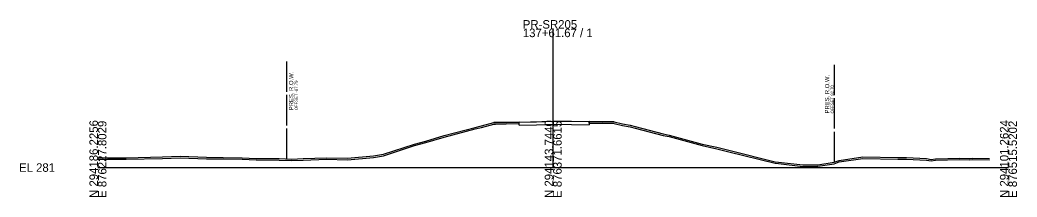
# Model space of a CAD drawing. Extents: x -26 to 875706, y -30 to 290725.
# Drawn here: x 2974.3 to 3302.8, y 2490.3 to 2548.5 of the extents above; entities that cross this region are included whole.
import ezdxf

# ---------------------------------------------------------------- set-up
doc = ezdxf.new("R2010")
doc.units = 0
for name, color, linetype in [('DESIGN - SHEET - Light Grid', 7, 'Continuous'), ('DESIGN - TYPICAL - Finished Grade and Subgrade', 7, 'Continuous'), ('SURVEY - GROUND - Bottom of Topsoil Layer', 7, 'Continuous'), ('SURVEY - GROUND - Existing Pavement Layer', 7, 'Continuous'), ('SURVEY - GROUND - Top of Ground', 7, 'Continuous'), ('SURVEY - PROPERTY - ROW Lines', 7, 'Continuous'), ('SURVEY - PROPERTY - ROW Lines Text', 7, 'Continuous')]:
    doc.layers.add(name, color=color, linetype=linetype)

msp = doc.modelspace()

# ---------------------------------------------------------------- linework, layer by layer
at = {"layer": 'DESIGN - SHEET - Light Grid'}
for p, q in [((3150, 2500), (3150, 2545.7)), ((3000, 2500), (3150, 2500)), ((3150, 2500), (3300, 2500))]:
    msp.add_line(p, q, dxfattribs=at)
at = {"layer": 'DESIGN - TYPICAL - Finished Grade and Subgrade'}
for p, q in [((3138.81, 2514.97), (3130.47, 2514.77)), ((3138.81, 2514.97), (3150, 2515.23)), ((3150, 2515.23), (3161.87, 2515.1)), ((3170.11, 2514.99), (3161.87, 2515.1))]:
    msp.add_line(p, q, dxfattribs=at)
msp.add_lwpolyline([(3139.41, 2514.98), (3139.41, 2514.97), (3139.42, 2514.97), (3139.42, 2514.98)], dxfattribs=at)
at = {"layer": 'SURVEY - GROUND - Bottom of Topsoil Layer'}
for p, q in [((3126.33, 2513.17), (3130.47, 2514.27)), ((3130.47, 2514.27), (3131.04, 2514.28)), ((3131.04, 2514.28), (3134.49, 2514.36)), ((3134.49, 2514.36), (3138.81, 2514.47)), ((3138.81, 2514.47), (3138.81, 2514.97)), ((3161.87, 2514.6), (3161.87, 2515.1)), ((3161.87, 2514.6), (3166.36, 2514.56)), ((3166.36, 2514.56), (3170.11, 2514.49)), ((3170.11, 2514.49), (3172.89, 2513.83)), ((3172.89, 2513.83), (3175.35, 2513.42)), ((3175.35, 2513.42), (3177.01, 2512.98)), ((3114.04, 2509.99), (3124.3, 2512.72)), ((3124.3, 2512.72), (3126.33, 2513.17)), ((3177.01, 2512.98), (3186.28, 2510.59)), ((3186.28, 2510.59), (3188.27, 2510.19)), ((3188.27, 2510.19), (3199.09, 2507.2)), ((3094.08, 2503.87), (3104.32, 2507.22)), ((3104.32, 2507.22), (3108.02, 2508.23)), ((3108.02, 2508.23), (3114.04, 2509.99)), ((3199.09, 2507.2), (3203.87, 2506.16)), ((3090.85, 2503.35), (3094.08, 2503.87)), ((3203.87, 2506.16), (3207.82, 2505.2)), ((3207.82, 2505.2), (3223.11, 2501.43)), ((3000, 2502.81), (3003.19, 2502.74)), ((3003.19, 2502.74), (3009.28, 2502.75)), ((3009.28, 2502.75), (3021.31, 2503.03)), ((3021.31, 2503.03), (3027.07, 2503.2)), ((3027.07, 2503.2), (3035.76, 2502.9)), ((3035.76, 2502.9), (3041.27, 2502.84)), ((3041.27, 2502.84), (3047.54, 2502.75)), ((3047.54, 2502.75), (3052.19, 2502.51)), ((3052.19, 2502.51), (3059.75, 2502.48)), ((3059.75, 2502.48), (3063.86, 2502.3)), ((3063.86, 2502.3), (3067.57, 2502.48)), ((3067.57, 2502.48), (3075.29, 2502.72)), ((3075.29, 2502.72), (3082.2, 2502.57)), ((3082.2, 2502.57), (3090.85, 2503.35)), ((3223.11, 2501.43), (3224.19, 2501.3)), ((3224.19, 2501.3), (3232.25, 2500.39)), ((3232.25, 2500.39), (3237.23, 2500.44)), ((3237.23, 2500.44), (3242.62, 2501.27)), ((3242.62, 2501.27), (3244.24, 2501.85)), ((3244.24, 2501.85), (3252.01, 2503)), ((3252.01, 2503), (3263.52, 2502.8)), ((3263.52, 2502.8), (3266.39, 2502.76)), ((3266.39, 2502.76), (3273.02, 2502.46)), ((3273.02, 2502.46), (3274.5, 2502.16)), ((3274.5, 2502.16), (3275.93, 2502.4)), ((3275.93, 2502.4), (3283.96, 2502.61)), ((3283.96, 2502.61), (3287.16, 2502.51)), ((3287.16, 2502.51), (3288.31, 2502.6)), ((3288.31, 2502.6), (3293.76, 2502.51))]:
    msp.add_line(p, q, dxfattribs=at)
at = {"layer": 'SURVEY - GROUND - Existing Pavement Layer'}
for p, q in [((3138.81, 2513.97), (3138.81, 2514.97)), ((3138.81, 2513.97), (3144.5, 2514.07)), ((3144.5, 2514.07), (3150.24, 2514.23)), ((3150.24, 2514.23), (3156.05, 2514.21)), ((3156.05, 2514.21), (3161.87, 2514.1)), ((3161.87, 2515.1), (3161.87, 2514.1))]:
    msp.add_line(p, q, dxfattribs=at)
at = {"layer": 'SURVEY - GROUND - Top of Ground'}
msp.add_lwpolyline([(3000, 2503.31), (3003.19, 2503.24), (3009.28, 2503.25), (3021.31, 2503.53), (3027.07, 2503.7), (3035.76, 2503.4), (3041.27, 2503.34), (3047.54, 2503.25), (3052.19, 2503.01), (3059.75, 2502.98), (3063.86, 2502.8), (3067.57, 2502.98), (3075.29, 2503.22), (3082.2, 2503.07), (3090.85, 2503.85), (3094.08, 2504.37), (3104.32, 2507.72), (3108.02, 2508.73), (3114.04, 2510.49), (3124.3, 2513.22), (3126.33, 2513.67), (3130.47, 2514.77), (3131.04, 2514.78), (3134.49, 2514.86), (3138.81, 2514.97), (3144.5, 2515.07), (3150.24, 2515.23), (3156.05, 2515.21), (3161.87, 2515.1), (3166.36, 2515.06), (3170.11, 2514.99), (3172.89, 2514.33), (3175.35, 2513.92), (3177.01, 2513.48), (3186.28, 2511.09), (3188.27, 2510.69), (3199.09, 2507.7), (3203.87, 2506.66), (3207.82, 2505.7), (3223.11, 2501.93), (3224.19, 2501.8), (3232.25, 2500.89), (3237.23, 2500.94), (3242.62, 2501.77), (3244.24, 2502.35), (3252.01, 2503.5), (3263.52, 2503.3), (3266.39, 2503.26), (3273.02, 2502.96), (3274.5, 2502.66), (3275.93, 2502.9), (3283.96, 2503.11), (3287.16, 2503.01), (3288.31, 2503.1), (3293.76, 2503.01)], dxfattribs=at)
at = {"layer": 'SURVEY - PROPERTY - ROW Lines'}
for p, q in [((3062.21, 2524.87), (3062.21, 2534.87)), ((3242.7, 2523.8), (3242.7, 2533.8)), ((3062.21, 2513.87), (3062.21, 2523.87)), ((3242.7, 2512.8), (3242.7, 2522.8)), ((3062.21, 2502.87), (3062.21, 2512.87)), ((3242.7, 2501.8), (3242.7, 2511.8))]:
    msp.add_line(p, q, dxfattribs=at)

# ---------------------------------------------------------------- texts
at = {"layer": 'DESIGN - SHEET - Light Grid'}
for s, p in [('PR-SR205', (3140, 2545.7)), ('137+61.67 / 1', (3140, 2542.9)), ('EL 281', (2974, 2498.6))]:
    msp.add_text(s, height=2.8, dxfattribs=at).set_placement(p)
for s, p in [('N 294186.2256', (3000, 2490)), ('E 876227.8029', (3002.8, 2490)), ('N 294143.7440', (3150, 2490)), ('E 876371.6615', (3152.8, 2490)), ('N 294101.2624', (3300, 2490)), ('E 876515.5202', (3302.8, 2490))]:
    msp.add_text(s, height=2.8, rotation=90, dxfattribs=at).set_placement(p)
at = {"layer": 'SURVEY - PROPERTY - ROW Lines Text'}
for s, height, p in [('PRES. R.O.W.', 1.4, (3064.36, 2518.87)), ('PRES. R.O.W.', 1.4, (3240.95, 2517.8)), ('OFFSET -87.79', 1, (3065.86, 2518.87)), ('OFFSET 92.70', 1, (3242.45, 2517.8))]:
    msp.add_text(s, height=height, rotation=90, dxfattribs=at).set_placement(p)

doc.saveas('drawing.dxf')
